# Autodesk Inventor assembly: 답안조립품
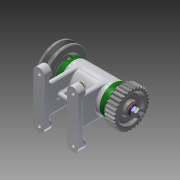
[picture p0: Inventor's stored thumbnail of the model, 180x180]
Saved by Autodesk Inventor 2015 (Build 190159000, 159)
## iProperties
Created: 2015-11
Part Number: 답안조립품
Document SubType Name: Assembly
Designer: Administrator
Author: Administrator
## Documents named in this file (15)
- C:\Users\Administrator\Desktop\451109V1034\답안조립품.iam
- C:\Users\Administrator\Desktop\451109V1034\본체.ipt
- C:\Users\Administrator\Desktop\451109V1034\커버.ipt
- C:\Users\Administrator\Desktop\451109V1034\베어링 15 x 32 x 9.ipt
- C:\Users\Administrator\Desktop\451109V1034\축.ipt
- C:\Users\Administrator\Desktop\451109V1034\오일 실 15 25 7.ipt
- C:\Users\Administrator\Desktop\451109V1034\와셔 6x11.5.ipt
- C:\Users\Administrator\Desktop\451109V1034\볼트 M 6 x 8.ipt
- C:\Users\Administrator\Desktop\451109V1034\볼트 M4 x 12.ipt
- C:\Users\Administrator\Desktop\451109V1034\키 3 x 3 x 12.ipt
- C:\Users\Administrator\Desktop\451109V1034\스퍼기어.ipt
- C:\Users\Administrator\Desktop\451109V1034\V벨트풀리.ipt
- C:\Users\Administrator\Desktop\451109V1034\와셔 8x17.ipt
- C:\Users\Administrator\Desktop\451109V1034\스프링와셔 8.ipt
- C:\Users\Administrator\Desktop\451109V1034\너트 M 8.ipt
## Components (11 placed, 3 different names)
1. KS B 2023 6002 - 15 x 32 x 9:1
2. KS B 2023 6002 - 15 x 32 x 9:2
3. ISO 4762 M4 x 12:1 — 각도:2
4. ISO 4762 M4 x 12:2 — 각도:3
5. ISO 4762 M4 x 12:3 — 각도:4
6. ISO 4762 M4 x 12:4 — 각도:5
7. ISO 4762 M4 x 12:5 — 각도:8
8. ISO 4762 M4 x 12:6 — 각도:9
9. ISO 4762 M4 x 12:7 — 각도:7
10. ISO 4762 M4 x 12:8 — 각도:6
11. V벨트풀리:1 — 각도:11
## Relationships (9: Angle 9)
- 각도:2 [Angle]: ISO 4762 M4 x 12:1
- 각도:3 [Angle]: ISO 4762 M4 x 12:2
- 각도:4 [Angle]: ISO 4762 M4 x 12:3
- 각도:5 [Angle]: ISO 4762 M4 x 12:4
- 각도:6 [Angle]: ISO 4762 M4 x 12:8
- 각도:7 [Angle]: ISO 4762 M4 x 12:7
- 각도:8 [Angle]: ISO 4762 M4 x 12:5
- 각도:9 [Angle]: ISO 4762 M4 x 12:6
- 각도:11 [Angle]: V벨트풀리:1
